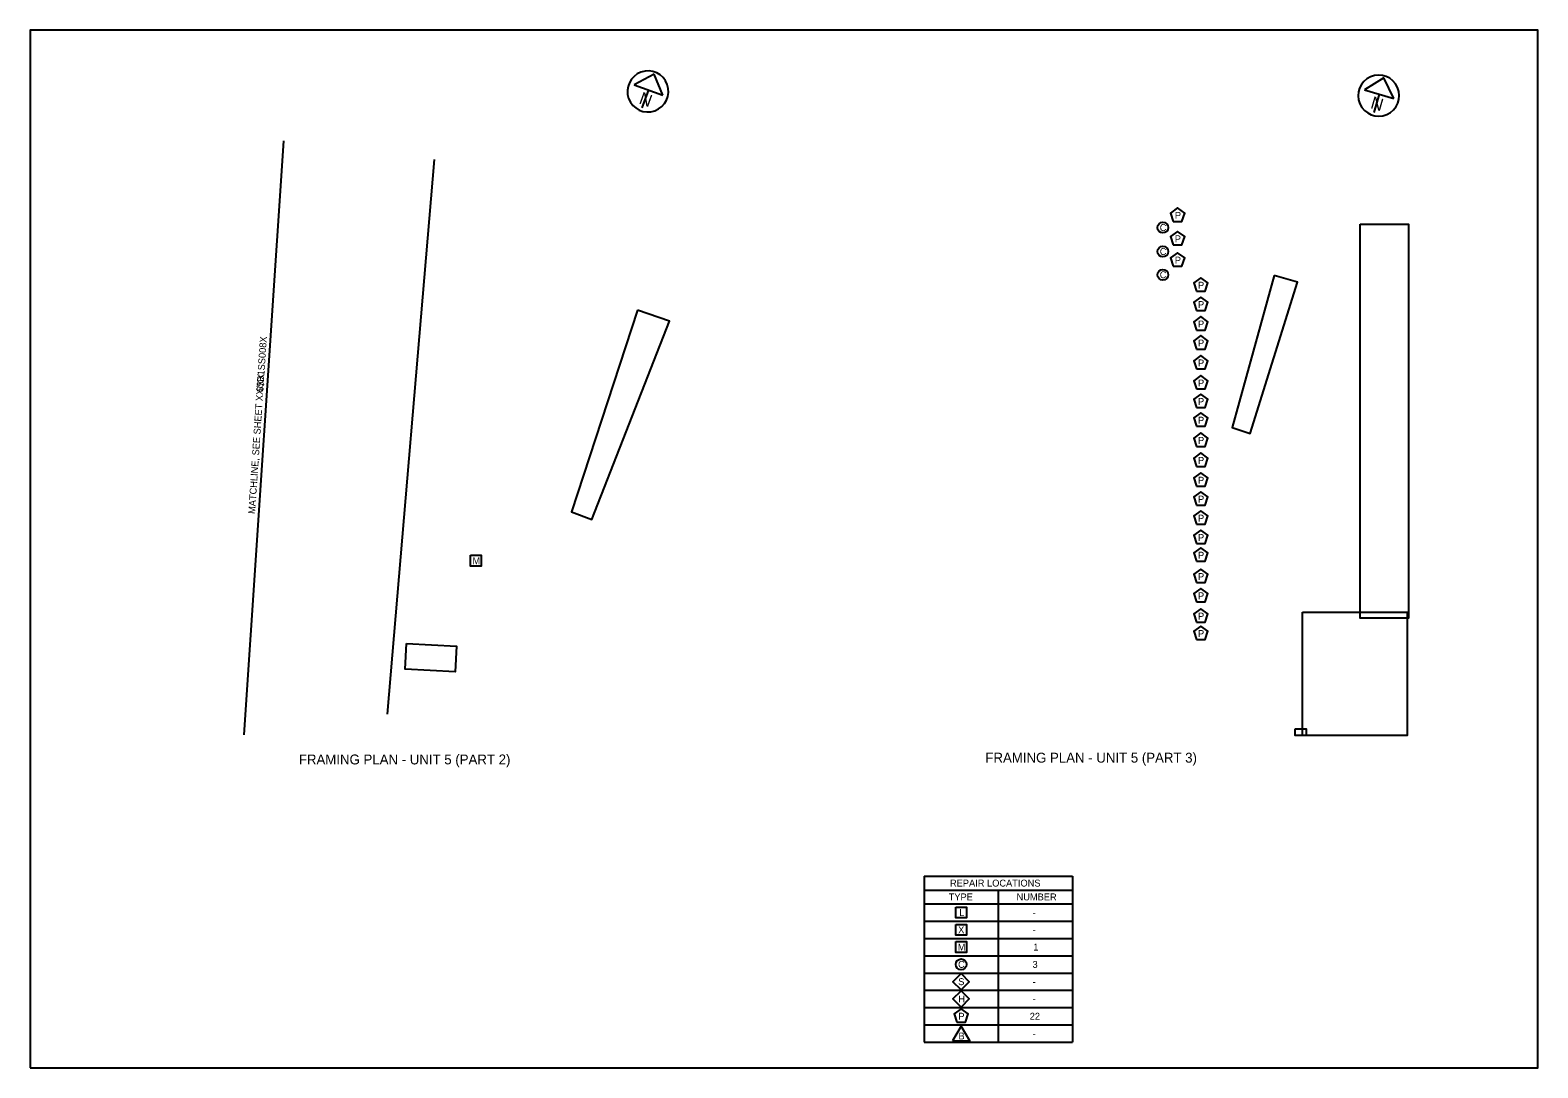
# Model space of a CAD drawing. Extents: x 100 to 130.5, y 100 to 121.
import ezdxf

# ---------------------------------------------------------------- set-up
doc = ezdxf.new("R2010")
doc.units = 0
for name, color, linetype in [('BR_P_Gen_Text', 7, 'Continuous'), ('BR_X_Sub_Centerline', 7, 'Continuous'), ('SC_Scratch1', 7, 'Continuous'), ('SH_Data', 7, 'Continuous'), ('SH_Masking', 7, 'Continuous')]:
    doc.layers.add(name, color=color, linetype=linetype)

msp = doc.modelspace()

# ---------------------------------------------------------------- linework, layer by layer
at = {"layer": 'BR_P_Gen_Text'}
for p, q in [((105.125, 118.759), (104.322, 106.741)), ((118.083, 103.879), (118.083, 100.519)), ((118.083, 103.879), (121.083, 103.879)), ((121.083, 103.879), (121.083, 100.519)), ((118.083, 103.599), (121.083, 103.599)), ((119.583, 103.599), (119.583, 100.519)), ((118.083, 103.319), (121.083, 103.319)), ((118.083, 102.969), (121.083, 102.969)), ((118.083, 102.619), (121.083, 102.619)), ((118.083, 102.269), (121.083, 102.269)), ((118.083, 101.919), (121.083, 101.919)), ((118.083, 101.569), (121.083, 101.569)), ((118.083, 101.219), (121.083, 101.219)), ((118.083, 100.869), (121.083, 100.869)), ((118.083, 100.519), (121.083, 100.519))]:
    msp.add_line(p, q, dxfattribs=at)
for points in [[(123.125, 117.13), (123.301, 117.13), (123.356, 117.298), (123.213, 117.402), (123.071, 117.298)], [(123.125, 116.655), (123.301, 116.655), (123.356, 116.823), (123.213, 116.926), (123.071, 116.823)], [(123.125, 116.223), (123.301, 116.223), (123.356, 116.391), (123.213, 116.495), (123.071, 116.391)], [(123.593, 115.716), (123.769, 115.716), (123.824, 115.884), (123.681, 115.987), (123.538, 115.884)], [(123.593, 115.325), (123.769, 115.325), (123.824, 115.493), (123.681, 115.596), (123.538, 115.493)], [(123.593, 114.931), (123.769, 114.931), (123.824, 115.099), (123.681, 115.203), (123.538, 115.099)], [(123.593, 114.546), (123.769, 114.546), (123.824, 114.714), (123.681, 114.818), (123.538, 114.714)], [(123.593, 114.144), (123.769, 114.144), (123.824, 114.311), (123.681, 114.415), (123.538, 114.311)], [(123.593, 113.738), (123.769, 113.738), (123.824, 113.906), (123.681, 114.01), (123.538, 113.906)], [(123.593, 113.364), (123.769, 113.364), (123.824, 113.532), (123.681, 113.635), (123.538, 113.532)], [(123.593, 112.985), (123.769, 112.985), (123.824, 113.152), (123.681, 113.256), (123.538, 113.152)], [(123.593, 112.576), (123.769, 112.576), (123.824, 112.744), (123.681, 112.848), (123.538, 112.744)], [(123.593, 112.171), (123.769, 112.171), (123.824, 112.339), (123.681, 112.443), (123.538, 112.339)], [(123.593, 111.77), (123.769, 111.77), (123.824, 111.938), (123.681, 112.041), (123.538, 111.938)], [(123.593, 111.387), (123.769, 111.387), (123.824, 111.555), (123.681, 111.659), (123.538, 111.555)], [(123.593, 111.002), (123.769, 111.002), (123.824, 111.17), (123.681, 111.274), (123.538, 111.17)], [(123.593, 110.61), (123.769, 110.61), (123.824, 110.778), (123.681, 110.882), (123.538, 110.778)], [(123.593, 110.252), (123.769, 110.252), (123.824, 110.42), (123.681, 110.524), (123.538, 110.42)], [(108.907, 110.373), (109.127, 110.373), (109.127, 110.153), (108.907, 110.153)], [(123.593, 109.821), (123.769, 109.821), (123.824, 109.988), (123.681, 110.092), (123.538, 109.988)], [(123.593, 109.431), (123.769, 109.431), (123.824, 109.599), (123.681, 109.702), (123.538, 109.599)], [(123.593, 109.02), (123.769, 109.02), (123.824, 109.188), (123.681, 109.292), (123.538, 109.188)], [(123.593, 108.668), (123.769, 108.668), (123.824, 108.836), (123.681, 108.939), (123.538, 108.836)], [(118.723, 103.254), (118.943, 103.254), (118.943, 103.034), (118.723, 103.034)], [(118.723, 102.904), (118.943, 102.904), (118.943, 102.684), (118.723, 102.684)], [(118.723, 102.554), (118.943, 102.554), (118.943, 102.334), (118.723, 102.334)], [(118.833, 101.909), (118.998, 101.744), (118.833, 101.579), (118.668, 101.744)], [(118.833, 101.559), (118.998, 101.394), (118.833, 101.229), (118.668, 101.394)], [(118.745, 100.923), (118.922, 100.923), (118.976, 101.091), (118.833, 101.194), (118.691, 101.091)], [(118.66, 100.544), (119.007, 100.544), (118.833, 100.844)]]:
    msp.add_lwpolyline(points, close=True, dxfattribs=at)
for centre in [(122.914, 117.005), (122.914, 116.52), (122.914, 116.049), (118.833, 102.094)]:
    msp.add_circle(centre, 0.11, dxfattribs=at)
at = {"layer": 'BR_X_Sub_Centerline'}
msp.add_line((107.232, 107.159), (108.177, 118.384), dxfattribs=at)
msp.add_lwpolyline([(107.614, 108.587), (108.625, 108.533), (108.597, 108.013), (107.586, 108.067)], close=True, dxfattribs=at)
at = {"layer": 'SC_Scratch1'}
msp.add_lwpolyline([(100, 100), (130.5, 100), (130.5, 121), (100, 121)], close=True, dxfattribs=at)
at = {"layer": 'SH_Data'}
for p, q in [((112.625, 120.11), (112.219, 119.895)), ((112.219, 119.895), (112.797, 119.684)), ((112.797, 119.684), (112.625, 120.11)), ((127.386, 120.034), (126.995, 119.793)), ((127.585, 119.62), (127.386, 120.034)), ((112.508, 119.79), (112.375, 119.426)), ((126.995, 119.793), (127.585, 119.62)), ((127.29, 119.707), (127.182, 119.335))]:
    msp.add_line(p, q, dxfattribs=at)
for centre, start, end in [((112.497, 119.759), 109.7139, 109.6974), ((127.281, 119.675), 113.5087, 113.4922)]:
    msp.add_arc(centre, 0.415, start, end, dxfattribs=at)
at = {"layer": 'SH_Masking'}
for points in [[(126.906, 117.071), (127.884, 117.071), (127.884, 109.097), (126.906, 109.097)], [(125.168, 116.038), (124.314, 112.962), (124.677, 112.834), (125.638, 115.903)], [(112.286, 115.334), (110.952, 111.251), (111.363, 111.095), (112.931, 115.112)], [(125.741, 109.225), (127.859, 109.225), (127.859, 106.724), (125.741, 106.724)], [(125.594, 106.86), (125.816, 106.86), (125.816, 106.729), (125.594, 106.729)]]:
    msp.add_lwpolyline(points, close=True, dxfattribs=at)

# ---------------------------------------------------------------- texts
at = {"layer": 'BR_P_Gen_Text'}
for s, height, p in [('P', 0.14, (123.157, 117.182)), ('C', 0.14, (122.851, 116.935)), ('P', 0.14, (123.157, 116.706)), ('C', 0.14, (122.851, 116.45)), ('P', 0.14, (123.157, 116.275)), ('C', 0.14, (122.851, 115.979)), ('P', 0.14, (123.625, 115.767)), ('P', 0.14, (123.625, 115.376)), ('P', 0.14, (123.625, 114.983)), ('P', 0.14, (123.625, 114.598)), ('P', 0.14, (123.625, 114.195)), ('P', 0.14, (123.625, 113.79)), ('P', 0.14, (123.625, 113.415)), ('P', 0.14, (123.625, 113.036)), ('P', 0.14, (123.625, 112.628)), ('P', 0.14, (123.625, 112.223)), ('P', 0.14, (123.625, 111.821)), ('P', 0.14, (123.625, 111.439)), ('P', 0.14, (123.625, 111.054)), ('P', 0.14, (123.625, 110.662)), ('P', 0.14, (123.625, 110.304)), ('M', 0.14, (108.948, 110.193)), ('P', 0.14, (123.625, 109.872)), ('P', 0.14, (123.625, 109.482)), ('P', 0.14, (123.625, 109.072)), ('P', 0.14, (123.625, 108.719)), ('FRAMING PLAN - UNIT 5 (PART 2)', 0.2, (105.436, 106.141)), ('FRAMING PLAN - UNIT 5 (PART 3)', 0.2, (119.324, 106.177)), ('REPAIR LOCATIONS', 0.14, (118.608, 103.669)), ('TYPE', 0.14, (118.582, 103.389)), ('NUMBER', 0.14, (119.955, 103.389)), ('L', 0.14, (118.795, 103.074)), ('-', 0.14, (120.28, 103.074)), ('X', 0.14, (118.773, 102.724)), ('-', 0.14, (120.28, 102.724)), ('M', 0.14, (118.765, 102.374)), ('1', 0.14, (120.294, 102.374)), ('C', 0.14, (118.771, 102.024)), ('3', 0.14, (120.277, 102.024)), ('S', 0.14, (118.775, 101.674)), ('-', 0.14, (120.28, 101.674)), ('H', 0.14, (118.777, 101.324)), ('-', 0.14, (120.28, 101.324)), ('P', 0.14, (118.777, 100.974)), ('22', 0.14, (120.221, 100.974)), ('B', 0.14, (118.779, 100.574)), ('-', 0.14, (120.28, 100.624))]:
    msp.add_text(s, height=height, dxfattribs=at).set_placement(p)
for s, p in [('$$B1SS008X', (104.715, 113.675)), ('MATCHLINE, SEE SHEET XX/XX', (104.55, 111.206))]:
    msp.add_text(s, height=0.14, rotation=86.1762, dxfattribs=at).set_placement(p)
at = {"layer": 'SH_Data'}
for rotation, p in [(339.9341, (112.299, 119.521)), (343.7288, (127.099, 119.425))]:
    msp.add_text('N', height=0.25, rotation=rotation, dxfattribs=at).set_placement(p)

doc.saveas('drawing.dxf')
